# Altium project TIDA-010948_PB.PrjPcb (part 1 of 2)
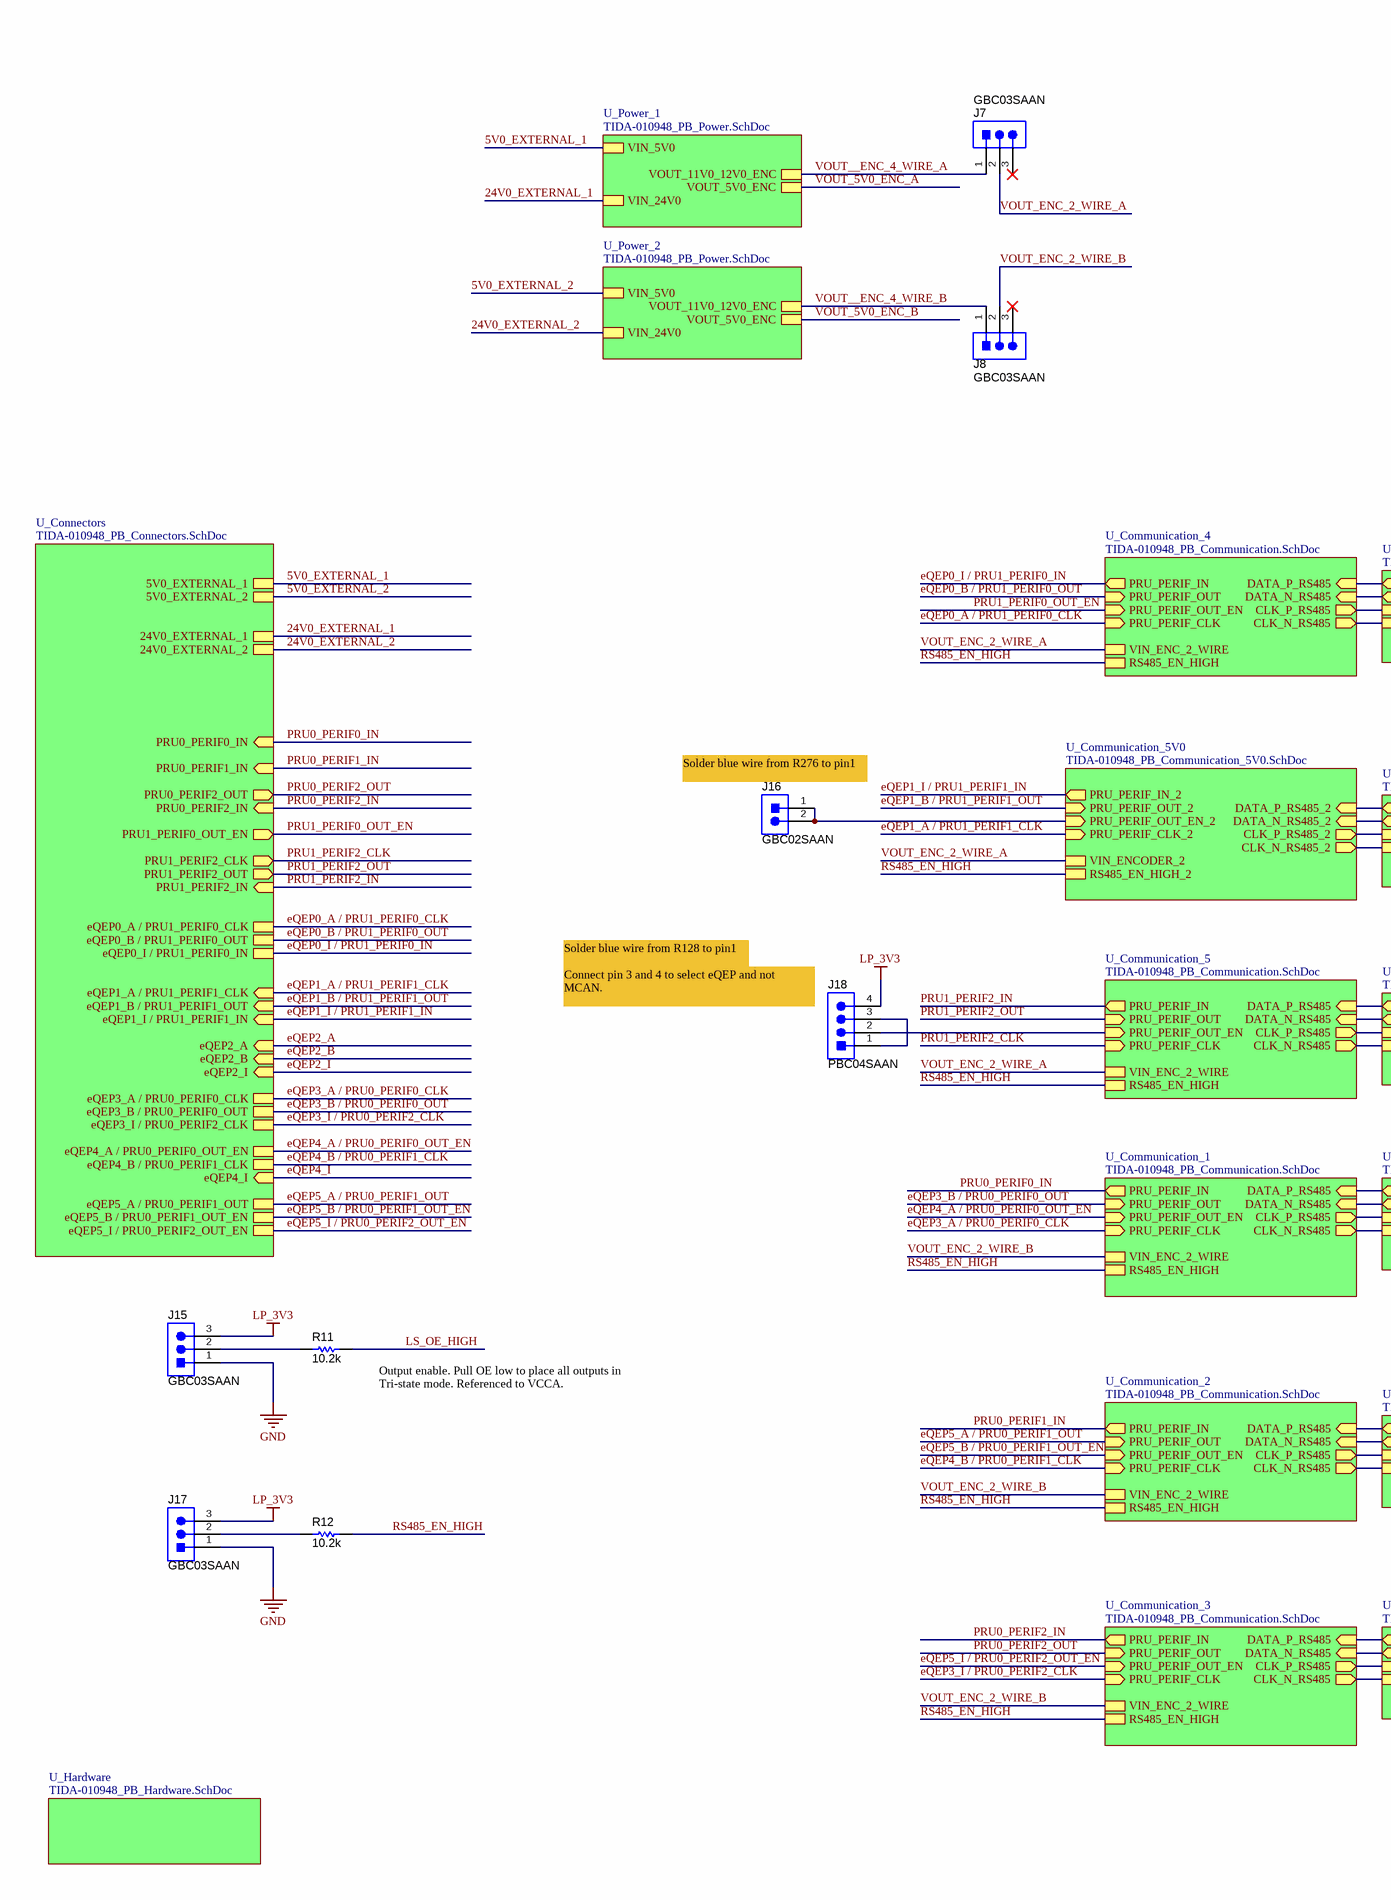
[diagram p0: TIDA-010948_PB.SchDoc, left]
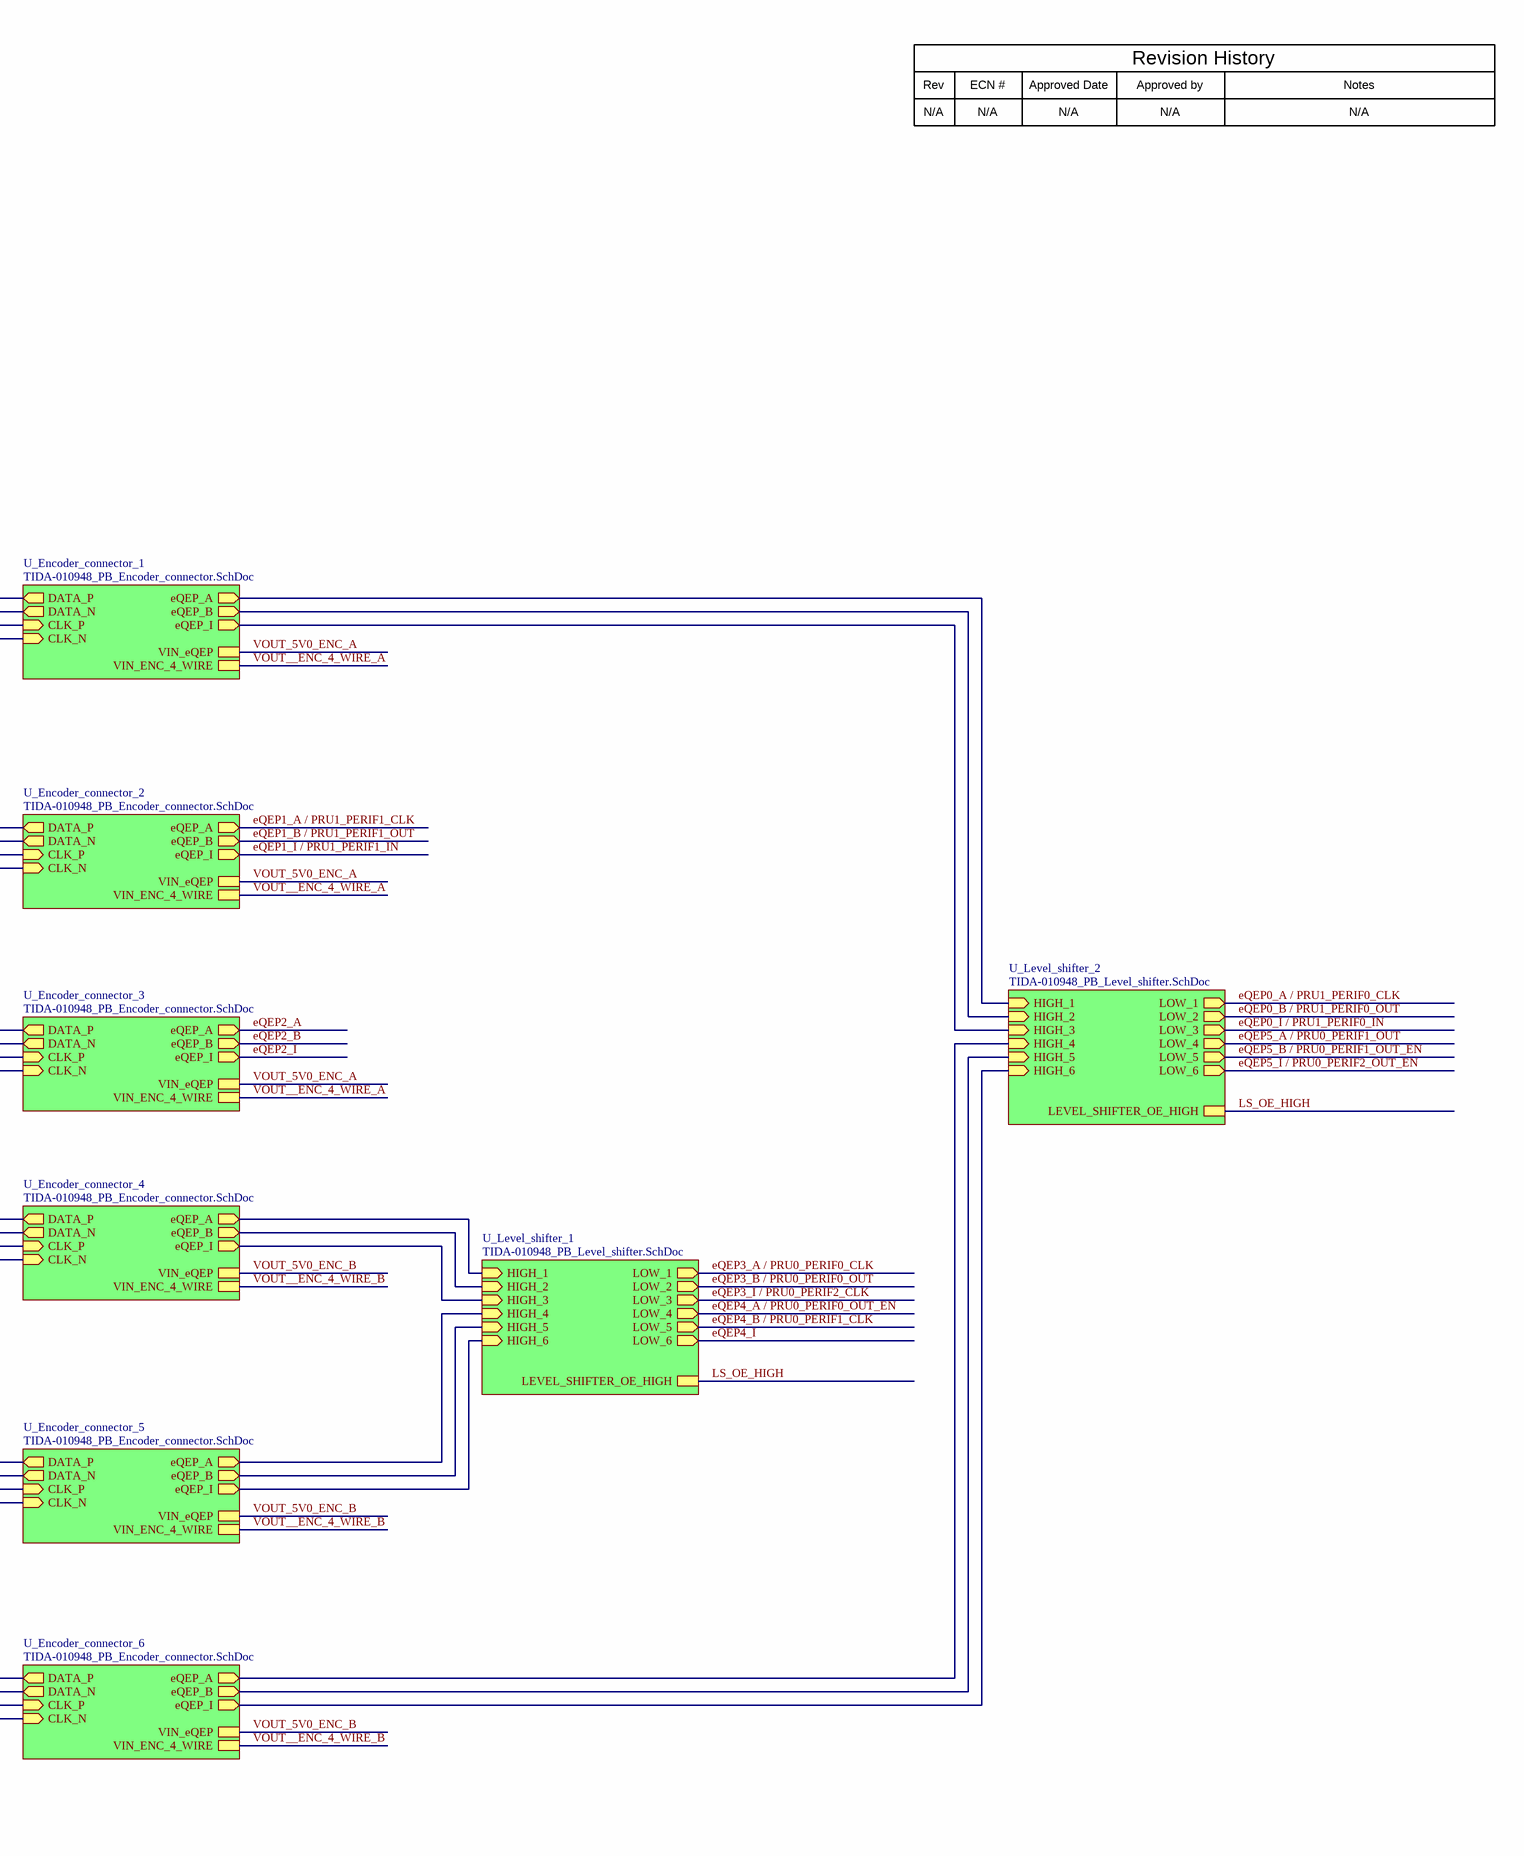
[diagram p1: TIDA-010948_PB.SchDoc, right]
TID: TIDA-010948-PB; TechSupport: http://www.ti.com/support; SCH_Rev: E1; PRJ_Title: TIDA-010948-PB; PRJ_Number: TIDA-010948-PB; PRJ_Engineer: Sabari Muthalagu; PRJ_Customer: Public Release; PCB_Rev: E1; PCB_Layout: Sabari Muthalagu; EVM_orderable: N/A; CopyrightYear: 2024
9 sheets, 482 parts. Net scope: hierarchical (ports join the sheet entries above them; power ports are global).
Board file: TIDA-010948_PB.PcbDoc
Sheets:
  TIDA-010948_PB.SchDoc
    U_Power_1 = TIDA-010948_PB_Power.SchDoc
      U_Buck_converters = TIDA-010948_PB_Buck_converters.SchDoc
    U_Communication_1 = TIDA-010948_PB_Communication.SchDoc
    U_Power_2 = TIDA-010948_PB_Power.SchDoc
      U_Buck_converters = TIDA-010948_PB_Buck_converters.SchDoc
    U_Communication_2 = TIDA-010948_PB_Communication.SchDoc
    U_Communication_3 = TIDA-010948_PB_Communication.SchDoc
    U_Communication_4 = TIDA-010948_PB_Communication.SchDoc
    U_Communication_5 = TIDA-010948_PB_Communication.SchDoc
    U_Connectors = TIDA-010948_PB_Connectors.SchDoc
    U_Encoder_connector_1 = TIDA-010948_PB_Encoder_connector.SchDoc
    U_Encoder_connector_2 = TIDA-010948_PB_Encoder_connector.SchDoc
    U_Encoder_connector_3 = TIDA-010948_PB_Encoder_connector.SchDoc
    U_Encoder_connector_4 = TIDA-010948_PB_Encoder_connector.SchDoc
    U_Encoder_connector_5 = TIDA-010948_PB_Encoder_connector.SchDoc
    U_Encoder_connector_6 = TIDA-010948_PB_Encoder_connector.SchDoc
    U_Level_shifter_1 = TIDA-010948_PB_Level_shifter.SchDoc
    U_Level_shifter_2 = TIDA-010948_PB_Level_shifter.SchDoc
    U_Communication_5V0 = TIDA-010948_PB_Communication_5V0.SchDoc
    U_Hardware = TIDA-010948_PB_Hardware.SchDoc

## Sheet TIDA-010948_PB.SchDoc
size A2; Date: Not shown in title block; ApprovedBy: Not shown in title block; CheckedBy: Not shown in title block; Author: Not shown in title block; CompanyName: Not shown in title block; Engineer: Not shown in title block; Organization: Not shown in title block; Address1: Not shown in title block; Address2: Not shown in title block; Address3: Not shown in title block; Address4: Not shown in title block; DocumentNumber: 1; Revision: Use project parameter SCH_Rev; SheetNumber: 1; SheetTotal: 9; PageSetup: Record=PageOptions¦CenterHorizontal=True¦CenterVertical=True¦PrintScale=0.69¦XCorrection=1.00¦YCorrection=1.00¦PrintKind=0¦BorderSize=5000000¦LeftOffset=0¦BottomOffset=0¦Orientation=2¦PaperLength=1000¦PaperWidth=1000¦Scale=100¦PaperSource=15¦PrintQuality=600¦MediaType=1¦DitherType=10¦PaperKind=Letter¦PrintScaleMode=1

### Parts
J7  GBC03SAAN  [Sullins_Gxx03SAAN]
J8  GBC03SAAN  [Sullins_Gxx03SAAN]
J15  GBC03SAAN  [Sullins_Gxx03SAAN]
J16  GBC02SAAN  [Sullins_Gxx02SAAN]
J17  GBC03SAAN  [Sullins_Gxx03SAAN]
J18  PBC04SAAN  [Sullins_xxC04SAAN]
R11  ValueDisplayed: 10.2k  [0603L]  (hidden comment: CRCW060310K2FKEA)
R12  ValueDisplayed: 10.2k  [0603L]  (hidden comment: CRCW060310K2FKEA)

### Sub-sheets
U_Communication_1 = TIDA-010948_PB_Communication.SchDoc: PRU_PERIF_IN (out), PRU_PERIF_OUT_EN (in), PRU_PERIF_OUT (in), PRU_PERIF_CLK (in), DATA_P_RS485 (in), DATA_N_RS485 (in), CLK_P_RS485 (out), CLK_N_RS485 (out), VIN_ENC_2_WIRE, RS485_EN_HIGH
U_Communication_2 = TIDA-010948_PB_Communication.SchDoc: PRU_PERIF_IN (out), PRU_PERIF_OUT_EN (in), PRU_PERIF_OUT (in), PRU_PERIF_CLK (in), DATA_P_RS485 (in), DATA_N_RS485 (in), CLK_P_RS485 (out), CLK_N_RS485 (out), VIN_ENC_2_WIRE, RS485_EN_HIGH
U_Communication_3 = TIDA-010948_PB_Communication.SchDoc: PRU_PERIF_IN (out), PRU_PERIF_OUT_EN (in), PRU_PERIF_OUT (in), PRU_PERIF_CLK (in), DATA_P_RS485 (in), DATA_N_RS485 (in), CLK_P_RS485 (out), CLK_N_RS485 (out), VIN_ENC_2_WIRE, RS485_EN_HIGH
U_Communication_4 = TIDA-010948_PB_Communication.SchDoc: PRU_PERIF_IN (out), PRU_PERIF_OUT_EN (in), PRU_PERIF_OUT (in), PRU_PERIF_CLK (in), DATA_P_RS485 (in), DATA_N_RS485 (in), CLK_P_RS485 (out), CLK_N_RS485 (out), VIN_ENC_2_WIRE, RS485_EN_HIGH
U_Communication_5 = TIDA-010948_PB_Communication.SchDoc: PRU_PERIF_IN (out), PRU_PERIF_OUT_EN (in), PRU_PERIF_OUT (in), PRU_PERIF_CLK (in), DATA_P_RS485 (in), DATA_N_RS485 (in), CLK_P_RS485 (out), CLK_N_RS485 (out), VIN_ENC_2_WIRE, RS485_EN_HIGH
U_Communication_5V0 = TIDA-010948_PB_Communication_5V0.SchDoc: PRU_PERIF_IN_2 (out), PRU_PERIF_OUT_EN_2 (in), PRU_PERIF_OUT_2 (in), PRU_PERIF_CLK_2 (in), VIN_ENCODER_2, RS485_EN_HIGH_2, DATA_P_RS485_2 (in), DATA_N_RS485_2 (in), CLK_P_RS485_2 (out), CLK_N_RS485_2 (out)
U_Connectors = TIDA-010948_PB_Connectors.SchDoc: eQEP2_A (in), eQEP2_B (in), eQEP2_I (in), eQEP1_A / PRU1_PERIF1_CLK (in), eQEP1_B / PRU1_PERIF1_OUT (in), eQEP1_I / PRU1_PERIF1_IN (in), PRU0_PERIF2_OUT (out), eQEP4_B / PRU0_PERIF1_CLK, eQEP5_A / PRU0_PERIF1_OUT, PRU0_PERIF0_IN (in), PRU0_PERIF1_IN (in), eQEP5_B / PRU0_PERIF1_OUT_EN, eQEP0_A / PRU1_PERIF0_CLK, eQEP3_A / PRU0_PERIF0_CLK, eQEP3_B / PRU0_PERIF0_OUT, eQEP4_A / PRU0_PERIF0_OUT_EN, eQEP4_I (in), PRU0_PERIF2_IN (in), eQEP0_B / PRU1_PERIF0_OUT, PRU1_PERIF0_OUT_EN (out), PRU1_PERIF2_CLK (out), PRU1_PERIF2_IN (in), PRU1_PERIF2_OUT (out), eQEP0_I / PRU1_PERIF0_IN, eQEP5_I / PRU0_PERIF2_OUT_EN, eQEP3_I / PRU0_PERIF2_CLK, 5V0_EXTERNAL_1, 5V0_EXTERNAL_2, 24V0_EXTERNAL_1, 24V0_EXTERNAL_2
U_Encoder_connector_1 = TIDA-010948_PB_Encoder_connector.SchDoc: DATA_N (out), DATA_P (out), CLK_N (in), CLK_P (in), eQEP_A (out), eQEP_B (out), eQEP_I (out), VIN_eQEP, VIN_ENC_4_WIRE
U_Encoder_connector_2 = TIDA-010948_PB_Encoder_connector.SchDoc: DATA_N (out), DATA_P (out), CLK_N (in), CLK_P (in), eQEP_A (out), eQEP_B (out), eQEP_I (out), VIN_eQEP, VIN_ENC_4_WIRE
U_Encoder_connector_3 = TIDA-010948_PB_Encoder_connector.SchDoc: DATA_N (out), DATA_P (out), CLK_N (in), CLK_P (in), eQEP_A (out), eQEP_B (out), eQEP_I (out), VIN_eQEP, VIN_ENC_4_WIRE
U_Encoder_connector_4 = TIDA-010948_PB_Encoder_connector.SchDoc: DATA_N (out), DATA_P (out), CLK_N (in), CLK_P (in), eQEP_A (out), eQEP_B (out), eQEP_I (out), VIN_eQEP, VIN_ENC_4_WIRE
U_Encoder_connector_5 = TIDA-010948_PB_Encoder_connector.SchDoc: DATA_N (out), DATA_P (out), CLK_N (in), CLK_P (in), eQEP_A (out), eQEP_B (out), eQEP_I (out), VIN_eQEP, VIN_ENC_4_WIRE
U_Encoder_connector_6 = TIDA-010948_PB_Encoder_connector.SchDoc: DATA_N (out), DATA_P (out), CLK_N (in), CLK_P (in), eQEP_A (out), eQEP_B (out), eQEP_I (out), VIN_eQEP, VIN_ENC_4_WIRE
U_Hardware = TIDA-010948_PB_Hardware.SchDoc: no entries
U_Level_shifter_1 = TIDA-010948_PB_Level_shifter.SchDoc: HIGH_1 (in), HIGH_2 (in), HIGH_3 (in), HIGH_4 (in), HIGH_5 (in), HIGH_6 (in), LOW_1 (out), LOW_2 (out), LOW_3 (out), LOW_4 (out), LOW_5 (out), LOW_6 (out), LEVEL_SHIFTER_OE_HIGH
U_Level_shifter_2 = TIDA-010948_PB_Level_shifter.SchDoc: HIGH_1 (in), HIGH_2 (in), HIGH_3 (in), HIGH_4 (in), HIGH_5 (in), HIGH_6 (in), LOW_1 (out), LOW_2 (out), LOW_3 (out), LOW_4 (out), LOW_5 (out), LOW_6 (out), LEVEL_SHIFTER_OE_HIGH
U_Power_1 = TIDA-010948_PB_Power.SchDoc: VOUT_11V0_12V0_ENC, VIN_5V0, VIN_24V0, VOUT_5V0_ENC
U_Power_2 = TIDA-010948_PB_Power.SchDoc: VOUT_11V0_12V0_ENC, VIN_5V0, VIN_24V0, VOUT_5V0_ENC

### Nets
GND: J15.1 J17.1
LP_3V3: J15.3 J17.3 J18.4
5V0_EXTERNAL_1: sheet U_Power_1/VIN_5V0, sheet U_Connectors/5V0_EXTERNAL_1
5V0_EXTERNAL_2: sheet U_Power_2/VIN_5V0, sheet U_Connectors/5V0_EXTERNAL_2
24V0_EXTERNAL_1: sheet U_Power_1/VIN_24V0, sheet U_Connectors/24V0_EXTERNAL_1
24V0_EXTERNAL_2: sheet U_Power_2/VIN_24V0, sheet U_Connectors/24V0_EXTERNAL_2
CLK_N: sheet U_Communication_1/CLK_N_RS485, sheet U_Encoder_connector_4/CLK_N
CLK_N: sheet U_Communication_2/CLK_N_RS485, sheet U_Encoder_connector_5/CLK_N  [a separate net that carries the same name]
CLK_N: sheet U_Communication_3/CLK_N_RS485, sheet U_Encoder_connector_6/CLK_N  [a separate net that carries the same name]
CLK_N: sheet U_Communication_4/CLK_N_RS485, sheet U_Encoder_connector_1/CLK_N  [a separate net that carries the same name]
CLK_N: sheet U_Communication_5/CLK_N_RS485, sheet U_Encoder_connector_3/CLK_N  [a separate net that carries the same name]
CLK_N: sheet U_Encoder_connector_2/CLK_N, sheet U_Communication_5V0/CLK_N_RS485_2  [a separate net that carries the same name]
CLK_P: sheet U_Communication_1/CLK_P_RS485, sheet U_Encoder_connector_4/CLK_P
CLK_P: sheet U_Communication_2/CLK_P_RS485, sheet U_Encoder_connector_5/CLK_P  [a separate net that carries the same name]
CLK_P: sheet U_Communication_3/CLK_P_RS485, sheet U_Encoder_connector_6/CLK_P  [a separate net that carries the same name]
CLK_P: sheet U_Communication_4/CLK_P_RS485, sheet U_Encoder_connector_1/CLK_P  [a separate net that carries the same name]
CLK_P: sheet U_Communication_5/CLK_P_RS485, sheet U_Encoder_connector_3/CLK_P  [a separate net that carries the same name]
CLK_P: sheet U_Encoder_connector_2/CLK_P, sheet U_Communication_5V0/CLK_P_RS485_2  [a separate net that carries the same name]
DATA_N: sheet U_Communication_1/DATA_N_RS485, sheet U_Encoder_connector_4/DATA_N
DATA_N: sheet U_Communication_2/DATA_N_RS485, sheet U_Encoder_connector_5/DATA_N  [a separate net that carries the same name]
DATA_N: sheet U_Communication_3/DATA_N_RS485, sheet U_Encoder_connector_6/DATA_N  [a separate net that carries the same name]
DATA_N: sheet U_Communication_4/DATA_N_RS485, sheet U_Encoder_connector_1/DATA_N  [a separate net that carries the same name]
DATA_N: sheet U_Communication_5/DATA_N_RS485, sheet U_Encoder_connector_3/DATA_N  [a separate net that carries the same name]
DATA_N: sheet U_Encoder_connector_2/DATA_N, sheet U_Communication_5V0/DATA_N_RS485_2  [a separate net that carries the same name]
DATA_P: sheet U_Communication_1/DATA_P_RS485, sheet U_Encoder_connector_4/DATA_P
DATA_P: sheet U_Communication_2/DATA_P_RS485, sheet U_Encoder_connector_5/DATA_P  [a separate net that carries the same name]
DATA_P: sheet U_Communication_3/DATA_P_RS485, sheet U_Encoder_connector_6/DATA_P  [a separate net that carries the same name]
DATA_P: sheet U_Communication_4/DATA_P_RS485, sheet U_Encoder_connector_1/DATA_P  [a separate net that carries the same name]
DATA_P: sheet U_Communication_5/DATA_P_RS485, sheet U_Encoder_connector_3/DATA_P  [a separate net that carries the same name]
DATA_P: sheet U_Encoder_connector_2/DATA_P, sheet U_Communication_5V0/DATA_P_RS485_2  [a separate net that carries the same name]
eQEP0_A / PRU1_PERIF0_CLK: sheet U_Communication_4/PRU_PERIF_CLK, sheet U_Connectors/eQEP0_A / PRU1_PERIF0_CLK, sheet U_Level_shifter_2/LOW_1
eQEP0_B / PRU1_PERIF0_OUT: sheet U_Communication_4/PRU_PERIF_OUT, sheet U_Connectors/eQEP0_B / PRU1_PERIF0_OUT, sheet U_Level_shifter_2/LOW_2
eQEP0_I / PRU1_PERIF0_IN: sheet U_Communication_4/PRU_PERIF_IN, sheet U_Connectors/eQEP0_I / PRU1_PERIF0_IN, sheet U_Level_shifter_2/LOW_3
eQEP1_A / PRU1_PERIF1_CLK: sheet U_Connectors/eQEP1_A / PRU1_PERIF1_CLK, sheet U_Encoder_connector_2/eQEP_A, sheet U_Communication_5V0/PRU_PERIF_CLK_2
eQEP1_B / PRU1_PERIF1_OUT: sheet U_Connectors/eQEP1_B / PRU1_PERIF1_OUT, sheet U_Encoder_connector_2/eQEP_B, sheet U_Communication_5V0/PRU_PERIF_OUT_2
eQEP1_I / PRU1_PERIF1_IN: sheet U_Connectors/eQEP1_I / PRU1_PERIF1_IN, sheet U_Encoder_connector_2/eQEP_I, sheet U_Communication_5V0/PRU_PERIF_IN_2
eQEP2_A: sheet U_Connectors/eQEP2_A, sheet U_Encoder_connector_3/eQEP_A
eQEP2_B: sheet U_Connectors/eQEP2_B, sheet U_Encoder_connector_3/eQEP_B
eQEP2_I: sheet U_Connectors/eQEP2_I, sheet U_Encoder_connector_3/eQEP_I
eQEP3_A / PRU0_PERIF0_CLK: sheet U_Communication_1/PRU_PERIF_CLK, sheet U_Connectors/eQEP3_A / PRU0_PERIF0_CLK, sheet U_Level_shifter_1/LOW_1
eQEP3_B / PRU0_PERIF0_OUT: sheet U_Communication_1/PRU_PERIF_OUT, sheet U_Connectors/eQEP3_B / PRU0_PERIF0_OUT, sheet U_Level_shifter_1/LOW_2
eQEP3_I / PRU0_PERIF2_CLK: sheet U_Communication_3/PRU_PERIF_CLK, sheet U_Connectors/eQEP3_I / PRU0_PERIF2_CLK, sheet U_Level_shifter_1/LOW_3
eQEP4_A / PRU0_PERIF0_OUT_EN: sheet U_Communication_1/PRU_PERIF_OUT_EN, sheet U_Connectors/eQEP4_A / PRU0_PERIF0_OUT_EN, sheet U_Level_shifter_1/LOW_4
eQEP4_B / PRU0_PERIF1_CLK: sheet U_Communication_2/PRU_PERIF_CLK, sheet U_Connectors/eQEP4_B / PRU0_PERIF1_CLK, sheet U_Level_shifter_1/LOW_5
eQEP4_I: sheet U_Connectors/eQEP4_I, sheet U_Level_shifter_1/LOW_6
eQEP5_A / PRU0_PERIF1_OUT: sheet U_Communication_2/PRU_PERIF_OUT, sheet U_Connectors/eQEP5_A / PRU0_PERIF1_OUT, sheet U_Level_shifter_2/LOW_4
eQEP5_B / PRU0_PERIF1_OUT_EN: sheet U_Communication_2/PRU_PERIF_OUT_EN, sheet U_Connectors/eQEP5_B / PRU0_PERIF1_OUT_EN, sheet U_Level_shifter_2/LOW_5
eQEP5_I / PRU0_PERIF2_OUT_EN: sheet U_Communication_3/PRU_PERIF_OUT_EN, sheet U_Connectors/eQEP5_I / PRU0_PERIF2_OUT_EN, sheet U_Level_shifter_2/LOW_6
eQEP_A: sheet U_Encoder_connector_1/eQEP_A, sheet U_Level_shifter_2/HIGH_1
eQEP_A: sheet U_Encoder_connector_4/eQEP_A, sheet U_Level_shifter_1/HIGH_1  [a separate net that carries the same name]
eQEP_A: sheet U_Encoder_connector_5/eQEP_A, sheet U_Level_shifter_1/HIGH_4  [a separate net that carries the same name]
eQEP_A: sheet U_Encoder_connector_6/eQEP_A, sheet U_Level_shifter_2/HIGH_4  [a separate net that carries the same name]
eQEP_B: sheet U_Encoder_connector_1/eQEP_B, sheet U_Level_shifter_2/HIGH_2
eQEP_B: sheet U_Encoder_connector_4/eQEP_B, sheet U_Level_shifter_1/HIGH_2  [a separate net that carries the same name]
eQEP_B: sheet U_Encoder_connector_5/eQEP_B, sheet U_Level_shifter_1/HIGH_5  [a separate net that carries the same name]
eQEP_B: sheet U_Encoder_connector_6/eQEP_B, sheet U_Level_shifter_2/HIGH_5  [a separate net that carries the same name]
eQEP_I: sheet U_Encoder_connector_1/eQEP_I, sheet U_Level_shifter_2/HIGH_3
eQEP_I: sheet U_Encoder_connector_4/eQEP_I, sheet U_Level_shifter_1/HIGH_3  [a separate net that carries the same name]
eQEP_I: sheet U_Encoder_connector_5/eQEP_I, sheet U_Level_shifter_1/HIGH_6  [a separate net that carries the same name]
eQEP_I: sheet U_Encoder_connector_6/eQEP_I, sheet U_Level_shifter_2/HIGH_6  [a separate net that carries the same name]
LS_OE_HIGH: R11.1 ; sheet U_Level_shifter_1/LEVEL_SHIFTER_OE_HIGH, sheet U_Level_shifter_2/LEVEL_SHIFTER_OE_HIGH
PRU0_PERIF0_IN: sheet U_Communication_1/PRU_PERIF_IN, sheet U_Connectors/PRU0_PERIF0_IN
PRU0_PERIF1_IN: sheet U_Communication_2/PRU_PERIF_IN, sheet U_Connectors/PRU0_PERIF1_IN
PRU0_PERIF2_IN: sheet U_Communication_3/PRU_PERIF_IN, sheet U_Connectors/PRU0_PERIF2_IN
PRU0_PERIF2_OUT: sheet U_Communication_3/PRU_PERIF_OUT, sheet U_Connectors/PRU0_PERIF2_OUT
PRU1_PERIF0_OUT_EN: sheet U_Communication_4/PRU_PERIF_OUT_EN, sheet U_Connectors/PRU1_PERIF0_OUT_EN
PRU1_PERIF2_CLK: sheet U_Communication_5/PRU_PERIF_CLK, sheet U_Connectors/PRU1_PERIF2_CLK
PRU1_PERIF2_IN: sheet U_Communication_5/PRU_PERIF_IN, sheet U_Connectors/PRU1_PERIF2_IN
PRU1_PERIF2_OUT: sheet U_Communication_5/PRU_PERIF_OUT, sheet U_Connectors/PRU1_PERIF2_OUT
PRU_PERIF_OUT_EN: J18.1 J18.2 J18.3 ; sheet U_Communication_5/PRU_PERIF_OUT_EN
PRU_PERIF_OUT_EN_2: J16.1 J16.2 ; sheet U_Communication_5V0/PRU_PERIF_OUT_EN_2
RS485_EN_HIGH: R12.1 ; sheet U_Communication_1/RS485_EN_HIGH, sheet U_Communication_2/RS485_EN_HIGH, sheet U_Communication_3/RS485_EN_HIGH, sheet U_Communication_4/RS485_EN_HIGH, sheet U_Communication_5/RS485_EN_HIGH, sheet U_Communication_5V0/RS485_EN_HIGH_2
VOUT_5V0_ENC_A: sheet U_Power_1/VOUT_5V0_ENC, sheet U_Encoder_connector_1/VIN_eQEP, sheet U_Encoder_connector_2/VIN_eQEP, sheet U_Encoder_connector_3/VIN_eQEP
VOUT_5V0_ENC_B: sheet U_Power_2/VOUT_5V0_ENC, sheet U_Encoder_connector_4/VIN_eQEP, sheet U_Encoder_connector_5/VIN_eQEP, sheet U_Encoder_connector_6/VIN_eQEP
VOUT__ENC_4_WIRE_A: J7.1 ; sheet U_Power_1/VOUT_11V0_12V0_ENC, sheet U_Encoder_connector_1/VIN_ENC_4_WIRE, sheet U_Encoder_connector_2/VIN_ENC_4_WIRE, sheet U_Encoder_connector_3/VIN_ENC_4_WIRE
VOUT__ENC_4_WIRE_B: J8.1 ; sheet U_Power_2/VOUT_11V0_12V0_ENC, sheet U_Encoder_connector_4/VIN_ENC_4_WIRE, sheet U_Encoder_connector_5/VIN_ENC_4_WIRE, sheet U_Encoder_connector_6/VIN_ENC_4_WIRE
VOUT_ENC_2_WIRE_A: J7.2 ; sheet U_Communication_4/VIN_ENC_2_WIRE, sheet U_Communication_5/VIN_ENC_2_WIRE, sheet U_Communication_5V0/VIN_ENCODER_2
VOUT_ENC_2_WIRE_B: J8.2 ; sheet U_Communication_1/VIN_ENC_2_WIRE, sheet U_Communication_2/VIN_ENC_2_WIRE, sheet U_Communication_3/VIN_ENC_2_WIRE
NetJ15_2: J15.2 R11.2
NetJ17_2: J17.2 R12.2

Not connected (* = marked no-connect by the designer): J7 3*; J8 3*

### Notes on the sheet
- Revision History
- Rev
- N/A
- ECN #
- Approved Date
- Approved by
- Notes
- (near J16) Solder blue wire from R276 to pin1
- Solder blue wire from R128 to pin1
- (near J18) Connect pin 3 and 4 to select eQEP and not MCAN.
  While using RS485 interface, connect pin 3 and 2.
- (near R11) Output enable. Pull OE low to place all outputs in Tri-state mode. Referenced to VCCA.

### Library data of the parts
J7 J8 J15 J17 = CMP-0054577-1: Header, 2.54 mm, 3x1, Gold, TH; Manufacturer: Sullins Connector Solutions; CT: FALSE; CNHeader: TRUE
J16 = CMP-0054576-1: Header, 2.54 mm, 2x1, Gold, TH; Manufacturer: Sullins Connector Solutions; CT: FALSE; CNHeader: TRUE
J18 = CMP-0054583-1: Header, 2.54 mm, 4x1, Gold, TH; Manufacturer: Sullins Connector Solutions; CNHeader: TRUE; Current_A: 3A; Green_Lifecycle: Not Set; Shrouded: N; Gender: Male; Green_REACh: Incomplete; Voltage_V: 1.8kV; Row_Count: 1; Pitch_mm: 2.54; CT: FALSE; Cert_UL: Y
R11 R12 = CMP-0021999-4: RES, 10.2 k, 1%, 0.1 W, AEC-Q200 Grade 0, 0603; Manufacturer: Vishay-Dale; Power_W: 100mW; TempCo: 100 ppm/C; Value_Code: 10k2; Value: 10.2k; EIA_Code: E96; SizeX_mm: 1.6; SizeY_mm: 0.8; SizeZ_mm: 1; Value2: 0.1W; SizeArea_mm2: 1.28; AEC Qualified: Y; VDC_V: 75V; AEC Category: Q200; AEC Grade: 0

## Sheet TIDA-010948_PB_Power.SchDoc
size A2; Date: Not shown in title block; ApprovedBy: Not shown in title block; CheckedBy: Not shown in title block; Author: Not shown in title block; CompanyName: Not shown in title block; Engineer: Not shown in title block; Organization: Not shown in title block; Address1: Not shown in title block; Address2: Not shown in title block; Address3: Not shown in title block; Address4: Not shown in title block; DocumentNumber: 1; Revision: Use project parameter SCH_Rev; SheetNumber: 4; SheetTotal: 9; PageSetup: Record=PageOptions¦CenterHorizontal=True¦CenterVertical=True¦PrintScale=0.69¦XCorrection=1.00¦YCorrection=1.00¦PrintKind=0¦BorderSize=5000000¦LeftOffset=0¦BottomOffset=0¦Orientation=2¦PaperLength=1000¦PaperWidth=1000¦Scale=100¦PaperSource=15¦PrintQuality=600¦MediaType=1¦DitherType=10¦PaperKind=Letter¦PrintScaleMode=1
Used 2 times, as channels U_Power_1, U_Power_2. Parts and nets are listed once, with the designators drawn on the sheet.
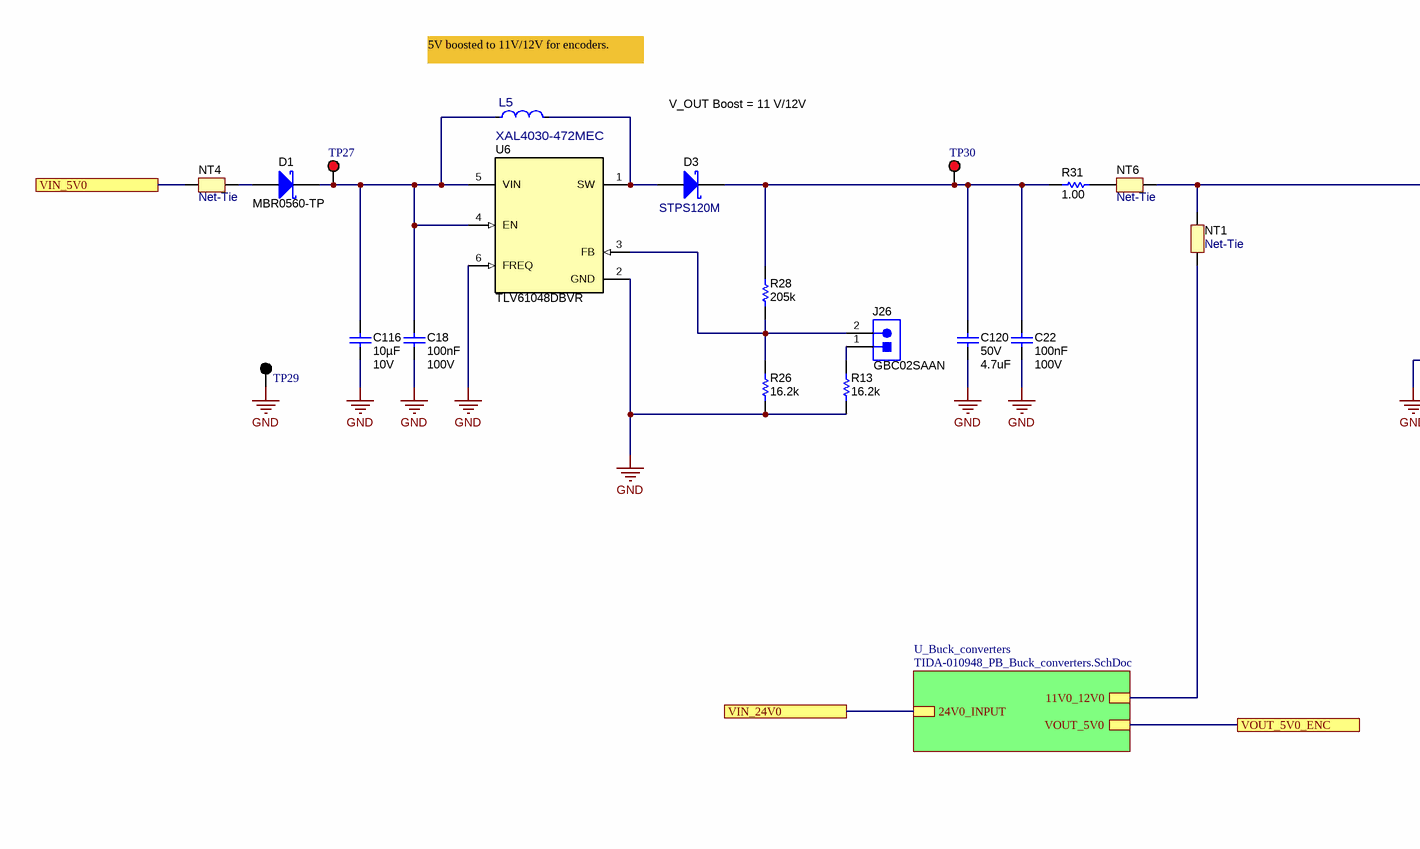
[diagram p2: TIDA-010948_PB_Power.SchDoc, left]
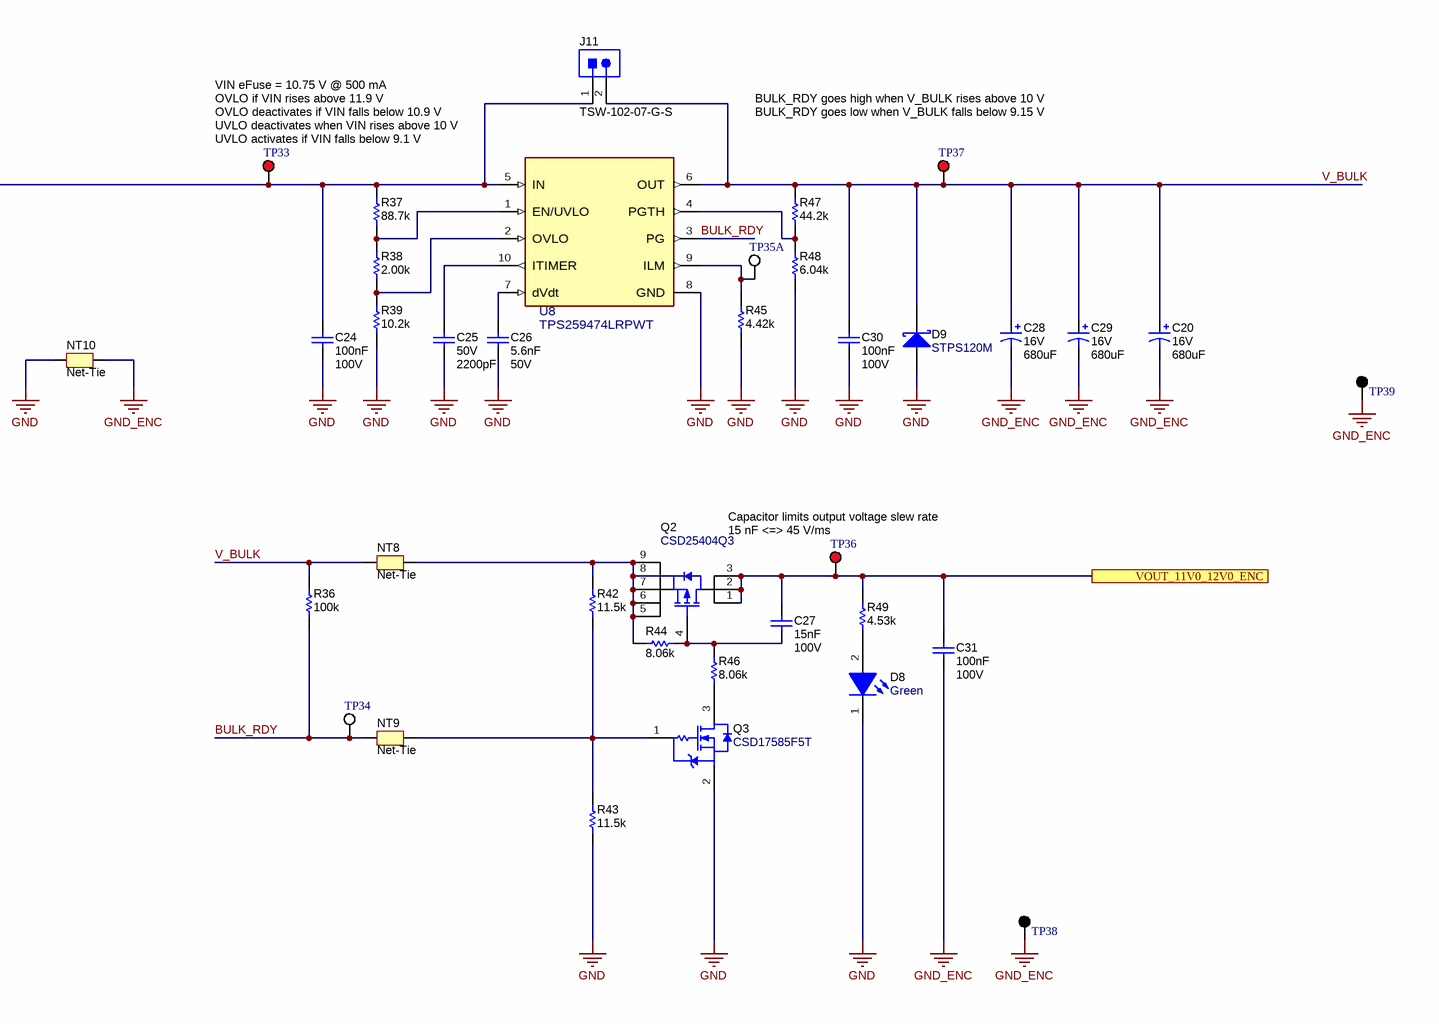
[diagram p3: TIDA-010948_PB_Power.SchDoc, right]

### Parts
C18  Cap_F: 100nF  VDC_V: 100V  [0603L]  (hidden comment: GRM188R72A104KA35D)
C20  VDC_V: 16V  ValueDisplayed: 680uF  [SM_RADIAL_G]  (hidden comment: EEE-FK1C681P)
C22  Cap_F: 100nF  VDC_V: 100V  [0603L]  (hidden comment: GRM188R72A104KA35D)
C24  Cap_F: 100nF  VDC_V: 100V  [0603L]  (hidden comment: GRM188R72A104KA35D)
C25  VDC_V: 50V  ValueDisplayed: 2200pF  [0603L]  (hidden comment: GRM1885C1H222JA01D)
C26  Cap_F: 5.6nF  VDC_V: 50V  [0603L]  (hidden comment: GRM188R71H562KA01D)
C27  Cap_F: 15nF  VDC_V: 100V  [0603L]  (hidden comment: GCM188R72A153KA37D)
C28  VDC_V: 16V  ValueDisplayed: 680uF  [SM_RADIAL_G]  (hidden comment: EEE-FK1C681P)
C29  VDC_V: 16V  ValueDisplayed: 680uF  [SM_RADIAL_G]  (hidden comment: EEE-FK1C681P)
C30  Cap_F: 100nF  VDC_V: 100V  [0603L]  (hidden comment: GRM188R72A104KA35D)
C31  Cap_F: 100nF  VDC_V: 100V  [0603L]  (hidden comment: GRM188R72A104KA35D)
C116  Cap_F: 10µF  VDC_V: 10V  [0805L]  (hidden comment: GRM21BR71A106KE51L)
C120  VDC_V: 50V  ValueDisplayed: 4.7uF  [0805L]  (hidden comment: GRM21BC71H475KE11K)
D1  MBR0560-TP  [SOD-123]
D3  STPS120M  [DO-216AA]
D8  value Green  [WL-SMCW_GREEN]  (hidden comment: 150060GS75000)
D9  STPS120M  [DO-216AA]
J11  TSW-102-07-G-S  [TSW-102-07-G-S]
J26  GBC02SAAN  [Sullins_Gxx02SAAN]
L5  XAL4030-472MEC  [FP-XAL4030-472MEC_SMD2-MFG]
NT1  Net-Tie  [Net-Tie_0805_HV_NoOverlay]  (net tie, no BOM)
NT4  Net-Tie  [Net-Tie_0805_HV_NoOverlay]  (net tie, no BOM)
NT6  Net-Tie  [Net-Tie_0805_HV_NoOverlay]  (net tie, no BOM)
NT8  Net-Tie  [Net-Tie_0805_HV_NoOverlay]  (net tie, no BOM)
NT9  Net-Tie  [Net-Tie_0805_HV_NoOverlay]  (net tie, no BOM)
NT10  Net-Tie  [Net-Tie_0805_HV_NoOverlay]  (net tie, no BOM)
Q2  CSD25404Q3  [DQG0008A]
Q3  CSD17585F5T  [YJK0003A]
R13  ValueDisplayed: 16.2k  [0603L]  (hidden comment: CRCW0603205KFKEA)
R26  ValueDisplayed: 16.2k  [0603L]  (hidden comment: CRCW060316K2FKEA)
R28  ValueDisplayed: 205k  [0603L]  (hidden comment: CRCW0603205KFKEA)
R31  ValueDisplayed: 1.00  [1206L]  (hidden comment: CRCW12061R00FKEA)
R36  ValueDisplayed: 100k  [0603L]  (hidden comment: CRCW0603100KFKEA)
R37  ValueDisplayed: 88.7k  [0603L]  (hidden comment: CRCW060388K7FKEA)
R38  ValueDisplayed: 2.00k  [0603L]  (hidden comment: CRCW06032K00FKEA)
R39  ValueDisplayed: 10.2k  [0603L]  (hidden comment: CRCW060310K2FKEA)
R42  ValueDisplayed: 11.5k  [0603L]  (hidden comment: CRCW060311K5FKEA)
R43  ValueDisplayed: 11.5k  [0603L]  (hidden comment: CRCW060311K5FKEA)
R44  ValueDisplayed: 8.06k  [0603L]  (hidden comment: CRCW06038K06FKEA)
R45  ValueDisplayed: 4.42k  [0603L]  (hidden comment: CRCW06034K42FKEA)
R46  ValueDisplayed: 8.06k  [0603L]  (hidden comment: CRCW06038K06FKEA)
R47  ValueDisplayed: 44.2k  [0603L]  (hidden comment: CRCW060344K2FKEA)
R48  ValueDisplayed: 6.04k  [0603L]  (hidden comment: CRCW06036K04FKEA)
R49  ValueDisplayed: 4.53k  [0603L]  (hidden comment: CRCW06034K53FKEA)
TP27  5000  [Keystone5000]  (value not drawn)
TP29  5001  [Keystone5001]  (value not drawn)
TP30  5000  [Keystone5000]  (value not drawn)
TP33  5000  [Keystone5000]  (value not drawn)
TP34  5002  [Keystone5002]  (value not drawn)
TP35A  5002  [Keystone5002]  (value not drawn)
TP36  5000  [Keystone5000]  (value not drawn)
TP37  5000  [Keystone5000]  (value not drawn)
TP38  5001  [Keystone5001]  (value not drawn)
TP39  5001  [Keystone5001]  (value not drawn)
U6  TLV61048DBVR  [DBV0006A_N]
U8  TPS259474LRPWT  [RPW0010A-MFG]

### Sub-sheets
U_Buck_converters = TIDA-010948_PB_Buck_converters.SchDoc: 24V0_INPUT, 11V0_12V0, VOUT_5V0

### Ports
VIN_5V0, VIN_24V0, VOUT_5V0_ENC, VOUT_11V0_12V0_ENC

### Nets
GND: C18.2 C22.2 C24.2 C25.2 C26.2 C30.2 C116.2 C120.2 D8.1(K) D9.2(A) NT10.1 Q3.2(S) R13.1 R26.1 R39.1 R43.1 R45.1 R48.1 TP29.1 U6.2(GND) U6.6(FREQ) U8.8(GND)
GND_ENC: C20.2(-) C28.2(-) C29.2(-) C31.2 NT10.2 TP38.1 TP39.1
BULK_RDY: NT9.1 R36.2 TP34.1 U8.3(PG)
V_BULK: C20.1(+) C28.1(+) C29.1(+) C30.1 D9.1(K) J11.2 NT8.1 R36.1 R47.2 TP37.1 U8.6(OUT)
VIN_5V0: NT4.1 ; port VIN_5V0
VIN_24V0: port VIN_24V0, sheet U_Buck_converters/24V0_INPUT
VOUT_5V0_ENC: port VOUT_5V0_ENC, sheet U_Buck_converters/VOUT_5V0
VOUT_11V0_12V0_ENC: C27.1 C31.1 Q2.1(D) Q2.2(D) Q2.3(D) R49.2 TP36.1 ; port VOUT_11V0_12V0_ENC
NetC18_1: C18.1 C116.1 D1.1(K) L5.1 TP27.1 U6.4(EN) U6.5(VIN)
NetC22_1: C22.1 C120.1 D3.1(K) R28.2 R31.1 TP30.1
NetC24_1: C24.1 J11.1 NT1.2 NT6.2 R37.2 TP33.1 U8.5(IN)
NetC25_1: C25.1 U8.10(ITIMER)
NetC26_1: C26.1 U8.7(dVdt)
NetC27_2: C27.2 Q2.4(G) R44.1 R46.2
NetD1_2: D1.2(A) NT4.2
NetD3_2: D3.2(A) L5.2 U6.1(SW)
NetD8_2: D8.2(A) R49.1
NetJ26_1: J26.1 R13.2
NetJ26_2: J26.2 R26.2 R28.1 U6.3(FB)
NetNT1_1: NT1.1 ; sheet U_Buck_converters/11V0_12V0
NetNT6_1: NT6.1 R31.2
NetNT8_2: NT8.2 Q2.5(S) Q2.6(S) Q2.7(S) Q2.8(S) Q2.9(S) R42.2 R44.2
NetNT9_2: NT9.2 Q3.1(G) R42.1 R43.2
NetQ3_3: Q3.3(D) R46.1
NetR37_1: R37.1 R38.2 U8.1(EN/UVLO)
NetR38_1: R38.1 R39.2 U8.2(OVLO)
NetR45_2: R45.2 TP35A.1 U8.9(ILM)
NetR47_1: R47.1 R48.2 U8.4(PGTH)

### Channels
U_Power_1: designators end in A; ports VIN_5V0=5V0_EXTERNAL_1 VIN_24V0=24V0_EXTERNAL_1 VOUT_5V0_ENC=VOUT_5V0_ENC_A VOUT_11V0_12V0_ENC=VOUT__ENC_4_WIRE_A
U_Power_2: designators end in B; ports VIN_5V0=5V0_EXTERNAL_2 VIN_24V0=24V0_EXTERNAL_2 VOUT_5V0_ENC=VOUT_5V0_ENC_B VOUT_11V0_12V0_ENC=VOUT__ENC_4_WIRE_B

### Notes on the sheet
- 5V boosted to 11V/12V for encoders.
- V_OUT Boost = 11 V/12V
- (near TP37) BULK_RDY goes high when V_BULK rises above 10 V
  BULK_RDY goes low when V_BULK falls below 9.15 V
- (near TP33) VIN eFuse = 10.75 V @ 500 mA
  OVLO if VIN rises above 11.9 V
  OVLO deactivates if VIN falls below 10.9 V
  UVLO deactivates when VIN rises above 10 V
  UVLO activates if VIN falls below 9.1 V
- Capacitor limits output voltage slew rate
  15 nF <=> 45 V/ms

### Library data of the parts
C18 C22 C24 C30 C31 = CMP-0007469-4: CAP, CERM, 0.1 uF, 100 V, +/- 10%, X7R, 0603; Manufacturer: MuRata; TaMin_C: -55°C; Polarized: N; SizeAreaWB_mm2: 4.68; Value1: Unknown; U/M: EA; Value: 0.1uF; TaMax_C: 125°C; SizeZ_mm: 1; SizeX_mm: 1.6; SizeY_mm: 0.8; Cap_Case: 0603; SizeArea_mm2: 1.28; AEC Category: Q200
C20 C28 C29 = CMP-0010708-1: CAP, AL, 680 uF, 16 V, +/- 20%, 0.08 ohm, AEC-Q200 Grade 2, SMD; Manufacturer: Panasonic; TaMin_C: -55°C; ESR_ohm: 0.08; Polarized: Y; SizeAreaWB_mm2: 172.2; U/M: EA; Value: 680uF; TaMax_C: 105°C; SizeZ_mm: 10.2; SizeX_mm: 12; SizeY_mm: 10.3; Cap_Case: G; SizeArea_mm2: 123.6; CompType: Capacitor; Cap_F: 680µF; IRMS_A: 850mA; AEC Grade: 2; AEC Category: Q200
C25 = CMP-0007198-4: CAP, CERM, 2200 pF, 50 V, +/- 5%, C0G/NP0, 0603; Manufacturer: MuRata; TaMin_C: -55°C; Polarized: N; SizeAreaWB_mm2: 4.68; Value1: Unknown; U/M: EA; Value: 2200pF; TaMax_C: 125°C; SizeZ_mm: 1; SizeX_mm: 1.6; SizeY_mm: 0.8; Cap_Case: 0603; SizeArea_mm2: 1.28; Cap_F: 2.2nF; AEC Category: Q200
C26 = CMP-0007459-4: CAP, CERM, 5600 pF, 50 V, +/- 10%, X7R, 0603; Manufacturer: MuRata; TaMin_C: -55°C; Polarized: N; SizeAreaWB_mm2: 4.68; Value1: Unknown; U/M: EA; Value: 5600pF; TaMax_C: 125°C; SizeZ_mm: 1; SizeX_mm: 1.6; SizeY_mm: 0.8; Cap_Case: 0603; SizeArea_mm2: 1.28; AEC Category: Q200
C27 = CMP-0007147-5: CAP, CERM, 0.015 uF, 100 V, +/- 10%, X7R, AEC-Q200 Grade 1, 0603; Manufacturer: MuRata; TaMin_C: -55°C; Polarized: N; SizeAreaWB_mm2: 4.68; Value1: Unknown; U/M: EA; TaMax_C: 125°C; SizeZ_mm: 1; SizeX_mm: 1.6; SizeY_mm: 0.8; Cap_Case: 0603; SizeArea_mm2: 1.28; AEC Qualified: Y; AEC Category: Q200
C116 = CMP-0008315-1: CAP, CERM, 10 uF, 10 V, +/- 10%, X7R, 0805; Manufacturer: MuRata; TaMin_C: -55°C; ESR_ohm: 3m; Polarized: N; SizeAreaWB_mm2: 6.75; Value1: 0.003 ohm; U/M: EA; Value: 10uF; TaMax_C: 125°C; SizeZ_mm: 1.45; SizeX_mm: 2; SizeY_mm: 1.25; Cap_Case: 0805; SizeArea_mm2: 2.5; AEC Category: Q200
C120 = CMP-0008264-1: CAP, CERM, 4.7 uF, 50 V, +/- 10%, X7S, 0805; Manufacturer: MuRata; TaMin_C: -55°C; Polarized: N; SizeAreaWB_mm2: 6.75; Value1: Unknown; U/M: EA; Value: 4.7uF; TaMax_C: 125°C; SizeZ_mm: 1.45; SizeX_mm: 2; SizeY_mm: 1.25; Cap_Case: 0805; SizeArea_mm2: 2.5; Cap_F: 4.7µF; AEC Category: Q200
D1 = CMP-0028602-3: Diode, Schottky, 60 V, 500 mA, SOD-123; Manufacturer: Micro Commercial Components; Vf_V: 700mV; SizeX_mm: 3.85; TJmax_C: 150°C; Green_Lifecycle: Not Set; Value2: 0.7V; AEC Category: Q101; Green_REACh: Incomplete; SizeZ_mm: 1.35; Io_A: 500mA; SizeAreaWB_mm2: 13.095; SizeArea_mm2: 6.545; Value1: 0.5A; Value: 60V; SizeY_mm: 1.7
D3 D9 = CMP-0077046-2: Diode, Schottky, 20 V, 1 A, DO-216-AA; Manufacturer: STMicroelectronics; AEC Category: Q101; SizeZ_mm: 1.15; SizeY_mm: 1.9; SizeArea_mm2: 7.144; SizeAreaWB_mm2: 13.804; Value: 20V; Green_REACh: Incomplete; SizeX_mm: 3.76; TJmax_C: 150°C; Green_Lifecycle: Not Set; Io_A: 1A; RJC_CperW: 20.0; Value2: 0.49V; Vf_V: 490mV
D8 = CMP-0002905-2: LED, Green, SMD; Manufacturer: Wurth Elektronik; Value1: W; Type: InGaN; Value2: 3.2V; Io_A: 20mA; Angle: 140; Tjmax_C: 85°C
J11 = CMP-0075405-3: Header, 100mil, 2x1, Gold, TH; Manufacturer: Samtec; Pitch_mm: 2.54; Cert_VDE: N; Gender: Male; Cert_CSA: Y; Voltage_V: 550V; Green_REACh: Passed; Current_A: 6.3A; Green_Lifecycle: Active; Row_Count: 1
J26 = CMP-0054576-1: as J16 on sheet TIDA-010948_PB
L5 = CMP-0089502-2: Power Inductor (SMD), 4.7 µH, 5.1 A, Shielded, 4.5 A, XAL40xx Series, 4mm x 4mm x 3.1mm; Manufacturer: Coilcraft; Isat: 4.5A; TaMax_C: +125°C; AEC Grade: Grade 1; Irms: 5.1A; DCR_ohm: 0.0441; Value: 4.7µH; Standoff Height: 0.08mm; Material: Composite; Tolerance_%: 20%; Self Resonant Frequency: 36MHz; AEC Qualified: Yes; Shrouded: true; Test Frequency: 1MHz; TaMin_C: -40°C
NT1 NT4 NT6 = CMP-0078142-4: Single point connection between nets.
NT8-NT10 = CMP-0078142-6: Single point connection between nets.
Q2 = CMP-0000026-3: MOSFET, P-CH, -20 V, -60 A, DQG0008A (VSON-CLIP-8); Manufacturer: Texas Instruments; Alternate Manufacturer: None; ChMode: Enhancement; SizeY_mm: 3.3; AEC Category: Q101; VdsMax_V: -20V; Value2: 10.8 nC; SizeZ_mm: 1.1; Value: -20V; SizeAreaWB_mm2: 18.49; AEC Qualified: N; IdsMax_A: -60A; SizeArea_mm2: 10.89; Vgs_V: -12V; QgTyp_nC: 10.8; Rdson45_ohm: 6.5m; Value1: 0.006; ChType: P
Q3 = CMP-0067551-1: MOSFET, N-CH, 30 V, 5.9 A, YJK0003A (PICOSTAR-3); Alternate Manufacturer: None; Manufacturer: Texas Instruments; Rdson45_ohm: 0.033; QgTyp_nC: 1.9; SizeAreaWB_mm2: 4.3077; Vgs_V: 20V; Value1: 0.033 ohm; VdsMax_V: 30V; U/M: EA; Value: 30V; IdsMax_A: 5.9A; SizeZ_mm: 0.35; SizeX_mm: 1.49; SizeY_mm: 0.73; Value2: 1.9 nC; SizeArea_mm2: 1.0877; ChType: N; AEC Category: Q101
R13 = CMP-0022202-4: RES, 205 k, 1%, 0.1 W, AEC-Q200 Grade 0, 0603; Manufacturer: Vishay-Dale; Power_W: 100mW; TempCo: 100 ppm/C; Value_Code: 205k; Value: 205k; EIA_Code: E96; SizeX_mm: 1.6; SizeY_mm: 0.8; SizeZ_mm: 1; Value2: 0.1W; SizeArea_mm2: 1.28; AEC Qualified: Y; VDC_V: 75V; AEC Category: Q200; AEC Grade: 0
R26 = CMP-0022079-4: RES, 16.2 k, 1%, 0.1 W, AEC-Q200 Grade 0, 0603; Manufacturer: Vishay-Dale; Power_W: 100mW; TempCo: 100 ppm/C; Value_Code: 16k2; Value: 16.2k; EIA_Code: E96; SizeX_mm: 1.6; SizeY_mm: 0.8; SizeZ_mm: 1; Value2: 0.1W; SizeArea_mm2: 1.28; AEC Qualified: Y; VDC_V: 75V; AEC Category: Q200; AEC Grade: 0
R28 = CMP-0022202-4: RES, 205 k, 1%, 0.1 W, AEC-Q200 Grade 0, 0603; Manufacturer: Vishay-Dale; Power_W: 100mW; TempCo: 100 ppm/C; Value: 205k; EIA_Code: E96; SizeX_mm: 1.6; SizeY_mm: 0.8; SizeZ_mm: 1; Value2: 0.1W; SizeArea_mm2: 1.28; AEC Qualified: Y; VDC_V: 75V; AEC Category: Q200; AEC Grade: 0
R31 = CMP-0016745-3: RES, 1.00, 1%, 0.25 W, AEC-Q200 Grade 0, 1206; Manufacturer: Vishay-Dale; Power_W: 250mW; TempCo: 100 ppm/C; Value_Code: 1R00; Value: 1.00; EIA_Code: E96; Res_ohm: 1; SizeX_mm: 3.2; SizeY_mm: 1.6; SizeZ_mm: 1.35; Value2: 0.25W; SizeArea_mm2: 5.12; AEC Qualified: Y; VDC_V: 200V; AEC Category: Q200; AEC Grade: 0
R36 = CMP-0021990-4: RES, 100 k, 1%, 0.1 W, AEC-Q200 Grade 0, 0603; Manufacturer: Vishay-Dale; Power_W: 100mW; TempCo: 100 ppm/C; Value: 100k; EIA_Code: E96; SizeX_mm: 1.6; SizeY_mm: 0.8; SizeZ_mm: 1; Value2: 0.1W; SizeArea_mm2: 1.28; AEC Qualified: Y; VDC_V: 75V; AEC Category: Q200; AEC Grade: 0
R37 = CMP-0022632-4: RES, 88.7 k, 1%, 0.1 W, AEC-Q200 Grade 0, 0603; Manufacturer: Vishay-Dale; Power_W: 100mW; TempCo: 100 ppm/C; Value_Code: 88k7; Value: 88.7k; EIA_Code: E96; SizeX_mm: 1.6; SizeY_mm: 0.8; SizeZ_mm: 1; Value2: 0.1W; SizeArea_mm2: 1.28; AEC Qualified: Y; VDC_V: 75V; AEC Category: Q200; AEC Grade: 0
R38 = CMP-0022268-4: RES, 2.00 k, 1%, 0.1 W, AEC-Q200 Grade 0, 0603; Manufacturer: Vishay-Dale; Power_W: 100mW; TempCo: 100 ppm/C; Value_Code: 2k00; Value: 2.00k; EIA_Code: E96; Res_ohm: 2k; SizeX_mm: 1.6; SizeY_mm: 0.8; SizeZ_mm: 1; Value2: 0.1W; SizeArea_mm2: 1.28; AEC Qualified: Y; VDC_V: 75V; AEC Category: Q200; AEC Grade: 0
R39 = CMP-0021999-4: as R11 on sheet TIDA-010948_PB
R42 R43 = CMP-0022018-4: RES, 11.5 k, 1%, 0.1 W, AEC-Q200 Grade 0, 0603; Manufacturer: Vishay-Dale; Power_W: 100mW; TempCo: 100 ppm/C; Value_Code: 11k5; Value: 11.5k; EIA_Code: E96; SizeX_mm: 1.6; SizeY_mm: 0.8; SizeZ_mm: 1; Value2: 0.1W; SizeArea_mm2: 1.28; AEC Qualified: Y; VDC_V: 75V; AEC Category: Q200; AEC Grade: 0
R44 R46 = CMP-0022634-4: RES, 8.06 k, 1%, 0.1 W, AEC-Q200 Grade 0, 0603; Manufacturer: Vishay-Dale; Power_W: 100mW; TempCo: 100 ppm/C; Value_Code: 8k06; Value: 8.06k; EIA_Code: E96; SizeX_mm: 1.6; SizeY_mm: 0.8; SizeZ_mm: 1; Value2: 0.1W; SizeArea_mm2: 1.28; AEC Qualified: Y; VDC_V: 75V; AEC Category: Q200; AEC Grade: 0
R45 = CMP-0022453-4: RES, 4.42 k, 1%, 0.1 W, AEC-Q200 Grade 0, 0603; Manufacturer: Vishay-Dale; Power_W: 100mW; TempCo: 100 ppm/C; Value_Code: 4k42; Value: 4.42k; EIA_Code: E96; SizeX_mm: 1.6; SizeY_mm: 0.8; SizeZ_mm: 1; Value2: 0.1W; SizeArea_mm2: 1.28; AEC Qualified: Y; VDC_V: 75V; AEC Category: Q200; AEC Grade: 0
R47 = CMP-0022426-4: RES, 44.2 k, 1%, 0.1 W, AEC-Q200 Grade 0, 0603; Manufacturer: Vishay-Dale; Power_W: 100mW; TempCo: 100 ppm/C; Value_Code: 44k2; Value: 44.2k; EIA_Code: E96; SizeX_mm: 1.6; SizeY_mm: 0.8; SizeZ_mm: 1; Value2: 0.1W; SizeArea_mm2: 1.28; AEC Qualified: Y; VDC_V: 75V; AEC Category: Q200; AEC Grade: 0
R48 = CMP-0022558-4: RES, 6.04 k, 1%, 0.1 W, AEC-Q200 Grade 0, 0603; Manufacturer: Vishay-Dale; Power_W: 100mW; TempCo: 100 ppm/C; Value_Code: 6k04; Value: 6.04k; EIA_Code: E96; SizeX_mm: 1.6; SizeY_mm: 0.8; SizeZ_mm: 1; Value2: 0.1W; SizeArea_mm2: 1.28; AEC Qualified: Y; VDC_V: 75V; AEC Category: Q200; AEC Grade: 0
R49 = CMP-0022454-4: RES, 4.53 k, 1%, 0.1 W, AEC-Q200 Grade 0, 0603; Manufacturer: Vishay-Dale; Power_W: 100mW; TempCo: 100 ppm/C; Value_Code: 4k53; Value: 4.53k; EIA_Code: E96; SizeX_mm: 1.6; SizeY_mm: 0.8; SizeZ_mm: 1; Value2: 0.1W; SizeArea_mm2: 1.28; AEC Qualified: Y; VDC_V: 75V; AEC Category: Q200; AEC Grade: 0
TP27 TP30 = CMP-0055137-1: Test Point, Miniature, Red, TH; Manufacturer: Keystone; CNHeader: FALSE; Green_Lifecycle: Active; Green_REACh: Passed; ContactFinish: Silver; CT: TRUE
TP29 = CMP-0055138-1: Test Point, Miniature, Black, TH; Manufacturer: Keystone; CNHeader: FALSE; Green_Lifecycle: Active; Green_REACh: Passed; ContactFinish: Silver; CT: TRUE
TP33 TP36 TP37 = CMP-0055137-2: Test Point, Miniature, Red, TH; Manufacturer: Keystone Electronics; CNHeader: FALSE; Green_Lifecycle: Active; Green_REACh: Passed; ContactFinish: Silver; CT: TRUE
TP34 TP35A = CMP-0055139-2: Test Point, Miniature, White, TH; Manufacturer: Keystone Electronics; CNHeader: FALSE; Green_Lifecycle: Active; Green_REACh: Passed; ContactFinish: Silver; CT: TRUE
TP38 TP39 = CMP-0055138-2: Test Point, Miniature, Black, TH; Manufacturer: Keystone Electronics; CNHeader: FALSE; Green_Lifecycle: Active; Green_REACh: Passed; ContactFinish: Silver; CT: TRUE
U6 = CMP-0085596-1: 15-V Output Voltage Non-Sync Boost Converter, DBV0006A (SOT-23-6); Alternate PartNumber: TLV61048DBVT; Alternate Manufacturer: Texas Instruments; SizeY_mm: 2.9; AEC Qualified: N; SizeArea_mm2: 8.12; SizeZ_mm: 1.45; SizeX_mm: 2.8; SizeAreaWB_mm2: 14.82; AEC Category: Q200; CompType: IC
U8 = CMP-0088329-1: 2.7- 23V, 5.5 A, 28 mΩ Reverse Current Blocking eFuse with Input Reverse Polarity Protection; Manufacturer: Texas Instruments; AEC Qualified: No; Nominal Supply Current: 0.5-6A; Threshold Voltage: 1.2/1.1V; Standoff Height: 0mm; Number Of Rails Monitored: 1; SizeZ_mm: 1mm; Min Supply Voltage: 2.7V; Reset Type: Active Low; TJmax_C: +125°C; Output Voltage: 42V

## Sheet TIDA-010948_PB_Buck_converters.SchDoc
size A2; Date: Not shown in title block; ApprovedBy: Not shown in title block; CheckedBy: Not shown in title block; Author: Not shown in title block; CompanyName: Not shown in title block; Engineer: Not shown in title block; Organization: Not shown in title block; Address1: Not shown in title block; Address2: Not shown in title block; Address3: Not shown in title block; Address4: Not shown in title block; DocumentNumber: 1; Revision: Use project parameter SCH_Rev; SheetNumber: 5; SheetTotal: 9; PageSetup: Record=PageOptions¦CenterHorizontal=True¦CenterVertical=True¦PrintScale=0.69¦XCorrection=1.00¦YCorrection=1.00¦PrintKind=0¦BorderSize=5000000¦LeftOffset=0¦BottomOffset=0¦Orientation=2¦PaperLength=1000¦PaperWidth=1000¦Scale=100¦PaperSource=15¦PrintQuality=600¦MediaType=1¦DitherType=10¦PaperKind=Letter¦PrintScaleMode=1
Used 2 times, as channels U_Power_1/U_Buck_converters, U_Power_2/U_Buck_converters. Parts and nets are listed once, with the designators drawn on the sheet.
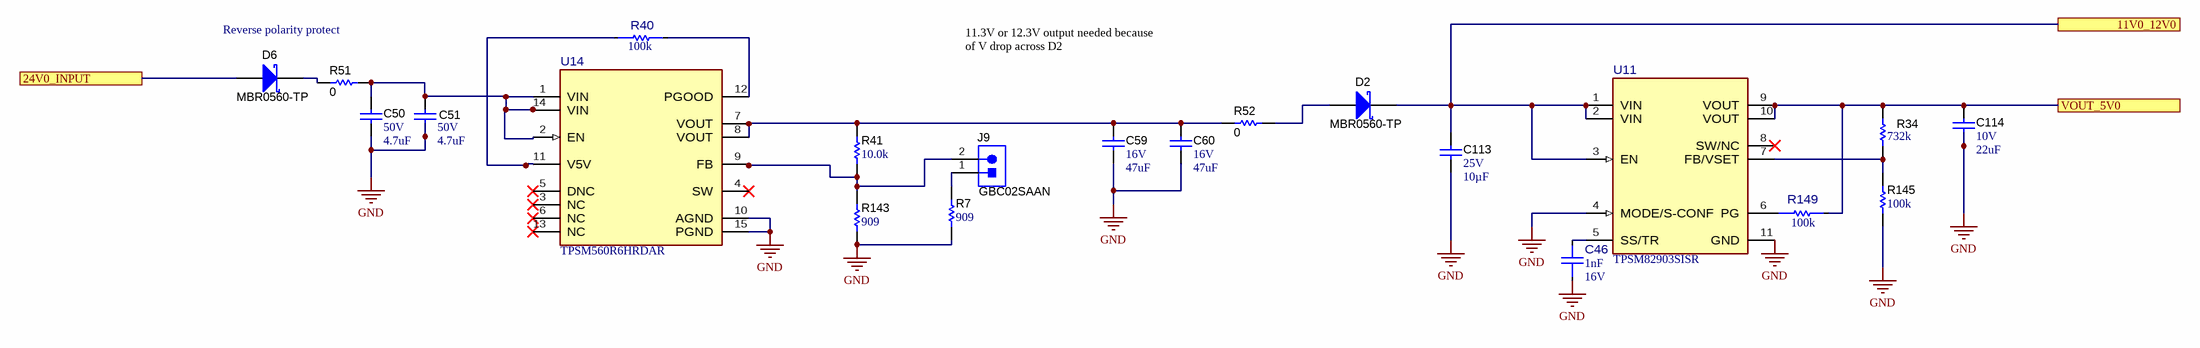
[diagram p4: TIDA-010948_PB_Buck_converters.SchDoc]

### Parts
C46  Cap_F: 1nF  VDC_V: 16V  [FP-CC0603KRX7R7BB102_0603-MFG]  (hidden comment: CC0603KRX7R7BB102)
C50  VDC_V: 50V  ValueDisplayed: 4.7uF  [0805_HV]  (hidden comment: GRM21BC71H475KE11K)
C51  VDC_V: 50V  ValueDisplayed: 4.7uF  [0805_HV]  (hidden comment: GRM21BC71H475KE11K)
C59  VDC_V: 16V  ValueDisplayed: 47uF  [1210_270]  (hidden comment: GRM32ER61C476KE15L)
C60  VDC_V: 16V  ValueDisplayed: 47uF  [1210_270]  (hidden comment: GRM32ER61C476KE15L)
C113  VDC_V: 25V  ValueDisplayed: 10µF  [1206_180]  (hidden comment: C3216X5R1E106K160AB)
C114  VDC_V: 10V  ValueDisplayed: 22uF  [0603]  (hidden comment: GRM187R61A226ME15D)
D2  MBR0560-TP  [SOD-123]
D6  MBR0560-TP  [SOD-123]
J9  GBC02SAAN  [Sullins_Gxx02SAAN]
R7  ValueDisplayed: 909  [0603]  (hidden comment: CRCW0603909RFKEA)
R34  ValueDisplayed: 732k  [0603]  (hidden comment: CRCW0603732KFKEA)
R40  value 100k  [FP-RE0201BRE07100KL_0201-MFG]  (hidden comment: RE0201BRE07100KL)
R41  ValueDisplayed: 10.0k  [0603]  (hidden comment: RNCF0603TKY10K0)
R51  ValueDisplayed: 0  [0603S]  (hidden comment: Resistor)
R52  ValueDisplayed: 0  [0603S]  (hidden comment: Resistor)
R143  ValueDisplayed: 909  [0603]  (hidden comment: CRCW0603909RFKEA)
R145  ValueDisplayed: 100k  [0603_HR]  (hidden comment: RR0816P-104-D)
R149  value 100k  [FP-RE0201BRE07100KL_0201-MFG]  (hidden comment: RE0201BRE07100KL)
U11  TPSM82903SISR  [SIS0011A-MFG]
U14  TPSM560R6HRDAR  [RDA0015A-MFG]

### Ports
11V0_12V0, 24V0_INPUT, VOUT_5V0

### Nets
GND: C46.1 C50.1 C51.1 C59.2 C60.1 C113.2 C114.2 R7.1 R143.1 R145.1 U11.4(MODE/S-CONF) U11.11(GND) U14.10(AGND) U14.15(PGND)
11V0_12V0: C113.1 D2.1(K) U11.1(VIN) U11.2(VIN) U11.3(EN) ; port 11V0_12V0
24V0_INPUT: D6.2(A) ; port 24V0_INPUT
VOUT_5V0: C114.1 R34.2 R149.2 U11.9(VOUT) U11.10(VOUT) ; port VOUT_5V0
NetC46_2: C46.2 U11.5(SS/TR)
NetC50_2: C50.2 C51.2 R51.1 U14.1(VIN) U14.2(EN) U14.14(VIN)
NetC59_1: C59.1 C60.2 R41.2 R52.2 U14.7(VOUT) U14.8(VOUT)
NetD2_2: D2.2(A) R52.1
NetD6_1: D6.1(K) R51.2
NetJ9_1: J9.1 R7.2
NetJ9_2: J9.2 R41.1 R143.2 U14.9(FB)
NetR34_1: R34.1 R145.2 U11.7(FB/VSET)
NetR40_1: R40.1 U14.11(V5V)
NetR40_2: R40.2 U14.12(PGOOD)
NetR149_1: R149.1 U11.6(PG)

Not connected (* = marked no-connect by the designer): U11 8(SW/NC)*; U14 3(NC)* 4(SW)* 5(DNC)* 6(NC)* 13(NC)*

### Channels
U_Power_1/U_Buck_converters: designators end in A; ports 11V0_12V0=11V0_12V0 24V0_INPUT=24V0_EXTERNAL_1 VOUT_5V0=VOUT_5V0_ENC_A
U_Power_2/U_Buck_converters: designators end in B; ports 11V0_12V0=11V0_12V0 24V0_INPUT=24V0_EXTERNAL_2 VOUT_5V0=VOUT_5V0_ENC_B

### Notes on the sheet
- Reverse polarity protect
- 11.3V or 12.3V output needed because of V drop across D2

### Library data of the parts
C46 = CMP-0094870-1: 1000 pF ±10% 16V Ceramic Capacitor X7R 0603 (1608 Metric); Manufacturer: YAGEO; AEC Qualified: No; Value: 1nF; ValueDisplayed: 1.0 nF; TempCo: 15%; SizeZ_mm: 0.9mm
C50 C51 = CMP-0008264-2: CAP, CERM, 4.7 uF, 50 V, +/- 10%, X7S, 0805; Manufacturer: MuRata; TaMin_C: -55°C; Polarized: N; SizeAreaWB_mm2: 6.75; Value1: Unknown; U/M: EA; Value: 4.7uF; TaMax_C: 125°C; SizeZ_mm: 1.45; SizeX_mm: 2; SizeY_mm: 1.25; Cap_Case: 0805; SizeArea_mm2: 2.5; Cap_F: 4.7µF; AEC Category: Q200
C59 C60 = CMP-0009211-1: CAP, CERM, 47 uF, 16 V, +/- 10%, X5R, 1210; Manufacturer: MuRata; TaMin_C: -55°C; Polarized: N; SizeAreaWB_mm2: 14.7; Value1: Unknown; U/M: EA; Value: 47uF; TaMax_C: 85°C; SizeZ_mm: 2.7; SizeX_mm: 3.2; SizeY_mm: 2.5; Cap_Case: 1210; SizeArea_mm2: 8; Cap_F: 47µF; AEC Category: Q200
C113 = CMP-0085573-1: CAP, CERM, 10 µF, 25 V,+/- 10%, X5R, 1206; Manufacturer: TDK; TaMin_C: -55°C; Polarized: N; SizeAreaWB_mm2: 10.92; U/M: EA; Value: 10uF; TaMax_C: 85°C; SizeZ_mm: 1.8; SizeX_mm: 3.2; SizeY_mm: 1.6; Cap_Case: 1206; SizeArea_mm2: 5.12; AEC Category: Q200; Green_REACh: Passed; Green_Lifecycle: Active
C114 = CMP-0007158-4: CAP, CERM, 22 uF, 10 V, +/- 20%, X5R, 0603; Manufacturer: MuRata; TaMin_C: -55°C; Polarized: N; SizeAreaWB_mm2: 4.68; Value1: Unknown; U/M: EA; Value: 22uF; TaMax_C: 85°C; SizeZ_mm: 1; SizeX_mm: 1.6; SizeY_mm: 0.8; SizeArea_mm2: 1.28; Cap_F: 22µF; AEC Category: Q200
D2 D6 = CMP-0028602-3: as D1 on sheet TIDA-010948_PB_Power
J9 = CMP-0054576-1: as J16 on sheet TIDA-010948_PB
R7 R143 = CMP-0022650-2: RES, 909, 1%, 0.1 W, 0603; Manufacturer: Vishay-Dale; Power_W: 100mW; TempCo: 100 ppm/C; Value_Code: 909R; U/M: EA; Value: 909; EIA_Code: E96; SizeX_mm: 1.6; SizeY_mm: 0.8; SizeZ_mm: 1; Value2: 0.1W; SizeArea_mm2: 1.28; VDC_V: 75V; AEC Category: Q200
R34 = CMP-0022583-4: RES, 732 k, 1%, 0.1 W, AEC-Q200 Grade 0, 0603; Manufacturer: Vishay-Dale; Power_W: 100mW; TempCo: 100 ppm/C; Value: 732k; EIA_Code: E96; SizeX_mm: 1.6; SizeY_mm: 0.8; SizeZ_mm: 1; Value2: 0.1W; SizeArea_mm2: 1.28; AEC Qualified: Y; VDC_V: 75V; AEC Category: Q200; AEC Grade: 0
R40 R149 = CMP-0120446-1: 100 kOhms ±0.1% 0.05W, 1/20W Chip Resistor 0201 (0603 Metric) Thick Film; Manufacturer: Yageo; Power_W: 50mW; TempCo: 50ppm/°C; SizeZ_mm: 0.26mm; AEC Qualified: No; VDC_V: 25V
R41 = CMP-0023626-1: RES, 10.0 k, 0.01%, 0.063 W, 0603; Manufacturer: Stackpole Electronics Inc; Power_W: 63mW; TempCo: 5 ppm/C; Value_Code: 10k0; U/M: EA; Value: 10.0k; Res_ohm: 10k; SizeX_mm: 1.6; SizeY_mm: 0.8; SizeZ_mm: 1; Value2: 0.063W; SizeArea_mm2: 1.28; VDC_V: 50V; AEC Category: Q200
R51 R52 = CMP-0025697-3: RES, 0, 5%, 0.1 W, 0603; PartNumber: CRCW06030000Z0EA; Manufacturer: Vishay-Dale; Value: 0; Value_Code: 0000; Power_W: 100mW; Value2: 0.1W; VDC_V: 75V; TempCo: 200 ppm/C; EIA_Code: E24; U/M: EA; SizeArea_mm2: 1.28; SizeX_mm: 1.6; SizeY_mm: 0.8; SizeZ_mm: 1; AEC Category: Q200
R145 = CMP-0065353-2: RES, 100 k, .5%, .0625 W, 0603; Manufacturer: Susumu Co Ltd; Power_W: 62.5mW; TempCo: 25 ppm/C; U/M: EA; Value: 100k; EIA_Code: E192; Tolerance_%: 0.5%; SizeX_mm: 1.55; SizeY_mm: 0.85; SizeZ_mm: 0.5; Value2: .0625W; SizeArea_mm2: 1.3175; AEC Qualified: N; VDC_V: 75V; AEC Category: Q200
U11 = CMP-0092464-2: 3-V to 17-V, High Efficiency and Low IQ Buck Converter Module in MicroSiP Package with Integrated Inductor; Manufacturer: Texas Instruments; Number Of Outputs: 1; TJmax_C: +125°C; SizeZ_mm: 1.6mm; Min Supply Voltage: 3V; Nominal Supply Current: 8mA; Max Duty Cycle: 100%; Output Type: AdjustableProgrammable; Output Voltage: 0.4-5.5V; Switching Frequency: 1/2.5MHz; AEC Category: Q200; AEC Qualified: No; CompType: IC; Max Supply Voltage: 17V
U14 = CMP-0092323-1: 60-V Input, 1-V to 16-V Output, 600-mA Power Module in Enhanced HotRod QFN Package; Manufacturer: Texas Instruments; SizeZ_mm: 4.1mm; Switching Topology: Buck; Switching Frequency: 1MHz; Min Supply Voltage: 4.2V; Output Voltage: 1-16V; TJmax_C: +125°C; TaMax_C: +105°C; TaMin_C: -55°C; Number Of Outputs: 1; Output Type: AdjustableProgrammable; Max Supply Voltage: 60V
